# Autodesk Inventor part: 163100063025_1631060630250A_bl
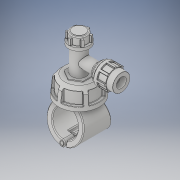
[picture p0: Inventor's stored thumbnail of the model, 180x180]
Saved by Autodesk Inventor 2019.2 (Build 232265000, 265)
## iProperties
Created: 2022-02
Part Number: 163100063025_1631060630250A_bl
Material: Generic
Description: Plassadle Tapper 63x25
Document SubType Name: Modeling
Designer: comp2
Density: 1 g/cm^3
Appearance: Default
Author: comp2
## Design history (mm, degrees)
derived "16310.ipt"
feature "Solid1::16310.ipt" dims "ScaleForDerivedMember" = 10
feature "Solid2::16310.ipt" dims "ScaleForDerivedMember" = 10
feature "Solid3::16310.ipt" dims "ScaleForDerivedMember" = 10
feature "Solid4::16310.ipt" dims "ScaleForDerivedMember" = 10
tag "TaggingFeature1"
body "Solid1"
body "Solid2"
body "Solid3"
body "Solid4"
other parameters: "d0" = 63 [user parameter], "d2" = 91 [user parameter], "d3" = 31.5 [user parameter], "d5" = 231 [user parameter], "d7" = 86.45 [user parameter], "d8" = 85 deg [user parameter], "d9" = 45 deg [user parameter], "d10" = 102 [user parameter], "d11" = 49 [user parameter], "d12" = 34.3 [user parameter], "d13" = 35.7 [user parameter], "d14" = 55.08 [user parameter], "d15" = 2.45 [user parameter], "d16" = 2 [user parameter], "d17" = 2 [user parameter], "d18" = 29.4 [user parameter], "d19" = 7.35 [user parameter], "d20" = 1 [user parameter], "d21" = 30.6 [user parameter], "d22" = 1 [user parameter], "d23" = 14.7 [user parameter], "d24" = 106 [user parameter], "d27" = 144 [user parameter], "d29" = 54 [user parameter], "d31" = 43.2 [user parameter], "d32" = 42.4 [user parameter], "d33" = 14.84 [user parameter], "d34" = 93 deg [user parameter], "d35" = 2 [user parameter], "d36" = 4 [user parameter], "d39" = 45 deg [user parameter], "d40" = 4 [user parameter], "d41" = 5 [user parameter], "d42" = 2.8 [user parameter], "d46" = 51 [user parameter], "d47" = 27 [user parameter], "d48" = 49 [user parameter], "d49" = 1.82 [user parameter], "d50" = 89 [user parameter], "d51" = 0 [user parameter], "d52" = 19.6 [user parameter], "d53" = 50.05 [user parameter], "d54" = 31.15 [user parameter], "d55" = 0 [user parameter], "d56" = 17.8 [user parameter], "d57" = 17.8 [user parameter], "d59" = 0 [user parameter], "d60" = 89 [user parameter], "d61" = 0 [user parameter], "d62" = 31.15 [user parameter], "d63" = 0 [user parameter], "d65" = 0 [user parameter], "d67" = 0 [user parameter], "d69" = 0 [user parameter], "d70" = 1 [user parameter], "d71" = 85.44 [user parameter], "d72" = 0 [user parameter], "d73" = 2 [user parameter], "d77" = 25 [user parameter], "d78" = 86.7 [user parameter], "d79" = 5.1 [user parameter], "d80" = 60 deg [user parameter], "d81" = 5.1 [user parameter], "d84" = 0 [user parameter], "d85" = 1 [user parameter], "d87" = 360 deg [user parameter], "d90" = 0 [user parameter], "d91" = 1 [user parameter], "d93" = 60 deg [user parameter], "d94" = 3.06 [user parameter], "d95" = 3.06 [user parameter], "d97" = 0 [user parameter], "d98" = 0.5 [user parameter], "d100" = 360 deg [user parameter], "d102" = 2 [user parameter], "d105" = 0 [user parameter], "d106" = 45 deg [user parameter], "d107" = 2.7 [user parameter], "d108" = 2.7 [user parameter], "d109" = 2.95332 [user parameter], "d110" = -8 [user parameter], "d112" = 0 [user parameter], "d113" = 0.5 [user parameter], "d115" = 360 deg [user parameter], "d117" = 0.5 [user parameter], "d" = 63 [user parameter], "d1" = 25 [user parameter], "B" = 91 [user parameter], "L" = 89 [user parameter], "E_" = 54 [user parameter], "E1" = 102 [user parameter], "H1" = 231 [user parameter], "H2" = 144 [user parameter], "H3" = 106 [user parameter], "H_costum" = 49 [user parameter]
